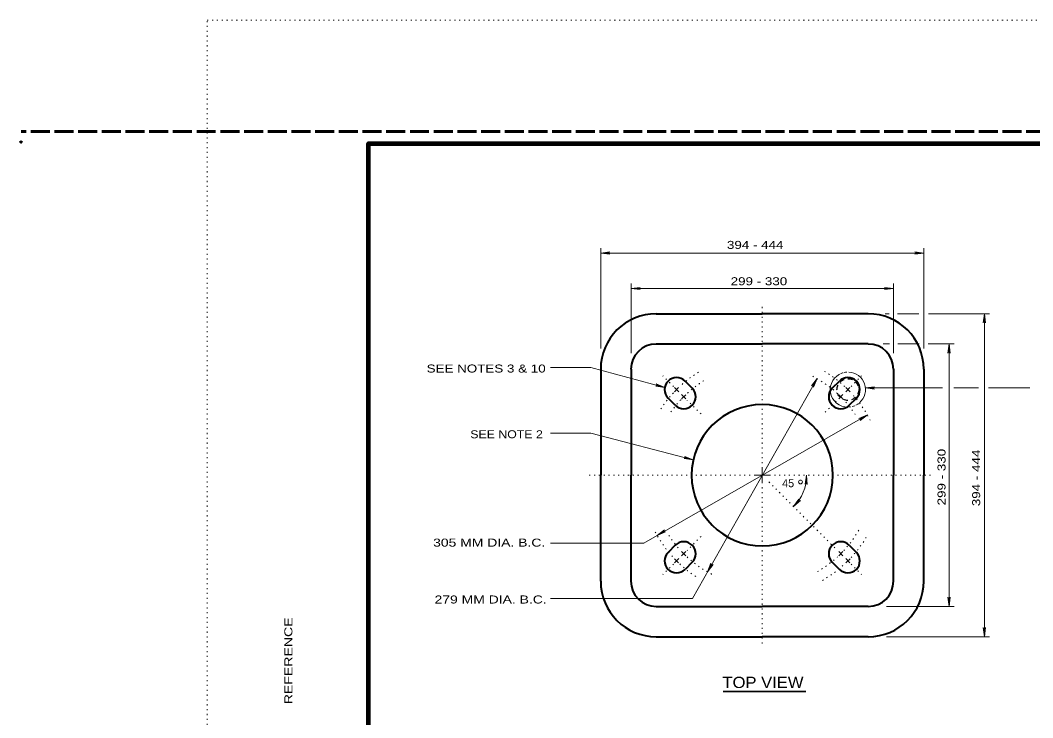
# Model space of a CAD drawing. Extents: x 312583 to 312854, y 144419 to 144597.
# Drawn here: x 312583.5 to 312679.6, y 144530.6 to 144596.8 of the extents above; entities that cross this region are included whole.
import ezdxf
from ezdxf.enums import TextEntityAlignment as Align

# ---------------------------------------------------------------- set-up
doc = ezdxf.new("R2010")
doc.units = 0
doc.header["$LTSCALE"] = 0.3
doc.header["$PDMODE"] = 32
doc.header["$PDSIZE"] = 0.15
for name, pattern in [('DOTTED', [1.5, 0.3, -1.2]), ('LONG_DASHED', [7.5, 6, -1.5]), ('SHORT_DASHED', [2.7, 1.5, -1.2])]:
    doc.linetypes.add(name, pattern=pattern)
for name, color, linetype, lineweight in [('1', 7, 'Continuous', 40), ('2', 7, 'Continuous', 13), ('62', 7, 'DOTTED', 13), ('63', 7, 'LONG_DASHED', 60)]:
    doc.layers.add(name, color=color, linetype=linetype, lineweight=lineweight)

msp = doc.modelspace()

# ---------------------------------------------------------------- linework, layer by layer
at = {"layer": '1'}
for p, q in [((312643.821, 144568.9263), (312653.8873, 144568.9263)), ((312663.946, 144568.9263), (312653.8873, 144568.9263)), ((312643.821, 144566.0513), (312653.8873, 144566.0513)), ((312663.946, 144566.0513), (312653.8873, 144566.0513)), ((312638.554, 144563.6516), (312638.554, 144553.5929)), ((312641.429, 144563.6516), (312641.429, 144553.5929)), ((312666.3457, 144563.6516), (312666.3457, 144553.5929)), ((312669.2207, 144563.6516), (312669.2207, 144553.5929)), ((312647.2327, 144561.8499), (312646.558, 144562.5246)), ((312660.5343, 144561.8499), (312661.209, 144562.5246)), ((312645.6227, 144560.2399), (312644.948, 144560.9146)), ((312662.1443, 144560.2399), (312662.819, 144560.9146)), ((312638.554, 144543.5266), (312638.554, 144553.5929)), ((312641.429, 144543.5266), (312641.429, 144553.5929)), ((312666.3457, 144543.5266), (312666.3457, 144553.5929)), ((312669.2207, 144543.5266), (312669.2207, 144553.5929)), ((312645.6227, 144546.9459), (312644.948, 144546.2636)), ((312662.1443, 144546.9459), (312662.819, 144546.2636)), ((312647.2327, 144545.3359), (312646.558, 144544.6536)), ((312660.5343, 144545.3359), (312661.209, 144544.6536)), ((312643.821, 144541.1346), (312653.8873, 144541.1346)), ((312663.946, 144541.1346), (312653.8873, 144541.1346)), ((312643.821, 144538.2596), (312653.8873, 144538.2596)), ((312663.946, 144538.2596), (312653.8873, 144538.2596))]:
    msp.add_line(p, q, dxfattribs=at)
at = {"layer": '1', "linetype": 'DOTTED', "lineweight": 13}
for p, q in [((312645.454, 144562.0186), (312644.4573, 144563.0229)), ((312662.313, 144562.0186), (312663.3097, 144563.0229)), ((312648.076, 144559.4043), (312646.742, 144560.7306)), ((312659.8597, 144559.5653), (312661.025, 144560.7306)), ((312654.5237, 144552.9489), (312661.025, 144546.4476)), ((312648.076, 144547.7816), (312646.742, 144546.4476)), ((312645.454, 144545.1596), (312644.4573, 144544.1629)), ((312662.313, 144545.1596), (312663.3097, 144544.1629))]:
    msp.add_line(p, q, dxfattribs=at)
at = {"layer": '1', "lineweight": 13}
for p, q in [((312645.96, 144561.5126), (312645.5537, 144561.9189)), ((312661.807, 144561.5126), (312662.2133, 144561.9189)), ((312646.6347, 144560.8456), (312646.2283, 144561.2519)), ((312661.14, 144560.8456), (312661.5463, 144561.2519)), ((312645.96, 144545.6733), (312645.5537, 144545.2669)), ((312646.6347, 144546.3403), (312646.2283, 144545.9339)), ((312661.14, 144546.3403), (312661.5463, 144545.9339)), ((312661.807, 144545.6733), (312662.2133, 144545.2669))]:
    msp.add_line(p, q, dxfattribs=at)
at = {"layer": '1', "lineweight": 158}
msp.add_lwpolyline([(312616.5, 144423.1446), (312616.5, 144585.0846), (312849, 144585.0846)], dxfattribs=at)
at = {"layer": '1', "linetype": 'SHORT_DASHED', "lineweight": 25}
msp.add_circle((312662.014, 144561.7215), 1.0339, dxfattribs=at)
at = {"layer": '1'}
for centre, radius, start, end in [((312643.821, 144563.6535), 5.2708, 90, 180), ((312663.946, 144563.6535), 5.2708, 0, 90), ((312643.821, 144563.6535), 2.3958, 90, 180), ((312663.946, 144563.6535), 2.3958, 0, 90), ((312645.753, 144561.7215), 1.1384, 45, 225), ((312662.014, 144561.7215), 1.1384, 315, 135), ((312646.4296, 144561.0449), 1.1384, 225, 45), ((312661.3374, 144561.0449), 1.1384, 135, 315), ((312653.8835, 144553.591), 6.7083, 90, 180), ((312653.8835, 144553.591), 6.7083, 0, 90), ((312653.8835, 144553.591), 6.7083, 180, 270), ((312653.8835, 144553.591), 6.7083, 270, 0), ((312646.4296, 144546.1371), 1.1384, 315, 135), ((312661.3374, 144546.1371), 1.1384, 45, 225), ((312645.753, 144545.4605), 1.1384, 135, 315), ((312662.014, 144545.4605), 1.1384, 225, 45), ((312643.821, 144543.5285), 5.2708, 180, 270), ((312643.821, 144543.5285), 2.3958, 180, 270), ((312663.946, 144543.5285), 5.2708, 270, 0), ((312663.946, 144543.5285), 2.3958, 270, 0)]:
    msp.add_arc(centre, radius, start, end, dxfattribs=at)
at = {"layer": '1', "linetype": 'DOTTED', "lineweight": 13}
for radius, start, end in [(11.5, 121.71451, 132.90639), (10.5417, 47.41661, 63.36905), (11.5, 47.09459, 60.18147), (10.5417, 121.71386, 132.58339), (11.5, 137.18158, 147.17965), (11.5, 26.95504, 42.81842), (10.5417, 137.23997, 147.17573), (10.5417, 33.10756, 42.76003), (11.5, 207.95114, 222.81842), (10.5417, 212.82427, 222.76003), (10.5417, 317.23939, 330.45291), (11.5, 317.18755, 330.45291), (10.5417, 227.41661, 243.86032), (10.5417, 299.81853, 312.58463), (11.5, 227.09361, 238.28549), (11.5, 299.81853, 312.90541)]:
    msp.add_arc((312653.8835, 144553.591), radius, start, end, dxfattribs=at)
at = {"layer": '1', "lineweight": 13}
for centre, radius, start, end in [((312662.014, 144561.7215), 1.6684, 119.0418, 280.06174), ((312662.014, 144561.7215), 1.6684, 105.69863, 115.35247), ((312662.014, 144561.7215), 1.6684, 93.2273, 102.59199), ((312662.014, 144561.7215), 1.6684, 311.02622, 87.10752), ((312653.8835, 144553.591), 11.5, 133.65585, 136.45218), ((312653.8835, 144553.591), 11.5, 43.54782, 46.34415), ((312653.8835, 144553.591), 10.5417, 133.51949, 136.65089), ((312653.8835, 144553.591), 10.5417, 43.34911, 46.48051), ((312662.014, 144561.7215), 1.6684, 284.29274, 293.24212), ((312662.014, 144561.7215), 1.6684, 297.30336, 307.05229), ((312653.8835, 144553.591), 11.5, 223.54782, 226.34415), ((312653.8835, 144553.591), 10.5417, 223.34911, 226.48051), ((312653.8835, 144553.591), 10.5417, 313.51949, 316.65089), ((312653.8835, 144553.591), 11.5, 313.65585, 316.45218)]:
    msp.add_arc(centre, radius, start, end, dxfattribs=at)
at = {"layer": '1'}
msp.add_point((312583.526, 144585.2246), dxfattribs=at)
at = {"layer": '2'}
for p, q in [((312638.554, 144565.6219), (312638.554, 144575.1593)), ((312638.554, 144574.6763), (312639.4203, 144574.7836)), ((312638.554, 144574.6763), (312669.2207, 144574.6763)), ((312638.554, 144574.6763), (312639.4203, 144574.5689)), ((312639.4203, 144574.7836), (312639.1443, 144574.6763)), ((312639.4203, 144574.5689), (312639.1443, 144574.6763)), ((312668.3543, 144574.7836), (312668.6303, 144574.6763)), ((312669.2207, 144574.6763), (312668.3543, 144574.7836)), ((312668.3543, 144574.5689), (312668.6303, 144574.6763)), ((312669.2207, 144574.6763), (312668.3543, 144574.5689)), ((312669.2207, 144565.6219), (312669.2207, 144575.1593)), ((312641.429, 144565.1849), (312641.429, 144571.8013)), ((312666.3457, 144565.1849), (312666.3457, 144571.8013)), ((312641.429, 144571.3183), (312642.2953, 144571.4256)), ((312641.429, 144571.3183), (312666.3457, 144571.3183)), ((312641.429, 144571.3183), (312642.2953, 144571.2109)), ((312642.2953, 144571.4256), (312642.0193, 144571.3183)), ((312642.2953, 144571.2109), (312642.0193, 144571.3183)), ((312665.4793, 144571.4256), (312665.7553, 144571.3183)), ((312666.3457, 144571.3183), (312665.4793, 144571.4256)), ((312665.4793, 144571.2109), (312665.7553, 144571.3183)), ((312666.3457, 144571.3183), (312665.4793, 144571.2109)), ((312665.5483, 144568.9263), (312665.9393, 144568.9263)), ((312666.7213, 144568.9263), (312668.7453, 144568.9263)), ((312669.673, 144568.9263), (312675.446, 144568.9263)), ((312674.9707, 144568.9263), (312674.8633, 144568.0599)), ((312674.9707, 144568.9263), (312674.9707, 144538.2596)), ((312674.9707, 144568.9263), (312675.078, 144568.0599)), ((312674.8633, 144568.0599), (312674.9707, 144568.3359)), ((312675.078, 144568.0599), (312674.9707, 144568.3359)), ((312665.349, 144566.0513), (312665.97, 144566.0513)), ((312666.752, 144566.0513), (312668.7837, 144566.0513)), ((312669.6423, 144566.0513), (312672.0957, 144566.0513)), ((312671.6127, 144566.0513), (312671.5053, 144565.1849)), ((312671.6127, 144566.0513), (312671.6127, 144541.1346)), ((312671.6127, 144566.0513), (312671.72, 144565.1849)), ((312671.5053, 144565.1849), (312671.6127, 144565.4609)), ((312671.72, 144565.1849), (312671.6127, 144565.4609)), ((312637.6263, 144563.8203), (312633.793, 144563.8203)), ((312644.6337, 144561.9343), (312637.6263, 144563.8203)), ((312643.775, 144562.0569), (312644.0663, 144562.0876)), ((312644.6337, 144561.9343), (312643.775, 144562.0569)), ((312643.8287, 144562.2639), (312644.0663, 144562.0876)), ((312644.6337, 144561.9343), (312643.8287, 144562.2639)), ((312647.2557, 144541.8936), (312659.0853, 144562.7623)), ((312659.0853, 144562.7623), (312658.564, 144562.0646)), ((312658.564, 144562.0646), (312658.794, 144562.2486)), ((312659.0853, 144562.7623), (312658.748, 144561.9573)), ((312658.748, 144561.9573), (312658.794, 144562.2486)), ((312663.6777, 144561.8729), (312664.544, 144561.9803)), ((312663.6777, 144561.8729), (312670.9917, 144561.8729)), ((312663.6777, 144561.8729), (312664.544, 144561.7656)), ((312664.544, 144561.9803), (312664.268, 144561.8729)), ((312664.544, 144561.7656), (312664.268, 144561.8729)), ((312672.0573, 144561.8729), (312674.411, 144561.8729)), ((312675.3693, 144561.8729), (312679.2947, 144561.8729)), ((312663.8617, 144559.3123), (312642.6557, 144547.1529)), ((312663.8617, 144559.3123), (312663.0567, 144558.9749)), ((312663.0567, 144558.9749), (312663.348, 144559.0209)), ((312663.8617, 144559.3123), (312663.164, 144558.7909)), ((312663.164, 144558.7909), (312663.348, 144559.0209)), ((312637.6263, 144557.5796), (312633.793, 144557.5796)), ((312647.3323, 144555.0496), (312637.6263, 144557.5796)), ((312646.4737, 144555.1646), (312646.765, 144555.1953)), ((312647.3323, 144555.0496), (312646.4737, 144555.1646)), ((312646.5273, 144555.3716), (312646.765, 144555.1953)), ((312647.3323, 144555.0496), (312646.5273, 144555.3716)), ((312653.8873, 144553.5929), (312653.8873, 144554.3596)), ((312653.8873, 144553.5929), (312653.8873, 144554.3596)), ((312653.8873, 144553.5929), (312653.1207, 144553.5929)), ((312653.8873, 144553.5929), (312654.654, 144553.5929)), ((312653.8873, 144553.5929), (312653.8873, 144552.8263)), ((312658.0963, 144553.5929), (312657.9507, 144552.7343)), ((312658.0963, 144553.5929), (312658.1577, 144552.7189)), ((312657.9507, 144552.7343), (312658.0657, 144553.0026)), ((312658.1577, 144552.7189), (312658.0657, 144553.0026)), ((312656.862, 144550.6106), (312657.368, 144551.3236)), ((312657.368, 144551.3236), (312657.2607, 144551.0476)), ((312656.862, 144550.6106), (312657.5213, 144551.1856)), ((312657.5213, 144551.1856), (312657.2607, 144551.0476)), ((312643.9053, 144547.8736), (312644.603, 144548.3949)), ((312644.603, 144548.3949), (312644.419, 144548.1649)), ((312643.9053, 144547.8736), (312644.7103, 144548.2109)), ((312644.7103, 144548.2109), (312644.419, 144548.1649)), ((312642.6557, 144547.1529), (312633.793, 144547.1529)), ((312648.6893, 144544.4236), (312649.019, 144545.2286)), ((312648.6893, 144544.4236), (312649.2107, 144545.1213)), ((312649.019, 144545.2286), (312648.9807, 144544.9373)), ((312649.2107, 144545.1213), (312648.9807, 144544.9373)), ((312647.2557, 144541.8936), (312633.793, 144541.8936)), ((312671.5053, 144542.0009), (312671.6127, 144541.7249)), ((312671.6127, 144541.1346), (312671.5053, 144542.0009)), ((312671.72, 144542.0009), (312671.6127, 144541.7249)), ((312671.6127, 144541.1346), (312671.72, 144542.0009)), ((312665.694, 144541.1346), (312672.0957, 144541.1346)), ((312674.8633, 144539.1259), (312674.9707, 144538.8499)), ((312674.9707, 144538.2596), (312674.8633, 144539.1259)), ((312675.078, 144539.1259), (312674.9707, 144538.8499)), ((312674.9707, 144538.2596), (312675.078, 144539.1259)), ((312665.694, 144538.2596), (312675.446, 144538.2596))]:
    msp.add_line(p, q, dxfattribs=at)
at = {"layer": '2', "linetype": 'DOTTED'}
for p, q in [((312653.8873, 144554.7429), (312653.8873, 144569.5856)), ((312652.7373, 144553.5929), (312637.4577, 144553.5929)), ((312655.0373, 144553.5929), (312670.0257, 144553.5929)), ((312653.8873, 144552.4429), (312653.8873, 144537.6003))]:
    msp.add_line(p, q, dxfattribs=at)
at = {"layer": '2', "lineweight": 35}
msp.add_line((312650.1687, 144533.0693), (312658.0158, 144533.0693), dxfattribs=at)
at = {"layer": '2'}
msp.add_circle((312657.5135, 144552.9508), 0.1797, dxfattribs=at)
msp.add_arc((312653.8835, 144553.591), 4.2148, 315, 0, dxfattribs=at)
at = {"layer": '62'}
for p, q in [((312601.2, 144596.7846), (312853.5, 144596.7846)), ((312601.2, 144418.5846), (312601.2, 144596.7846))]:
    msp.add_line(p, q, dxfattribs=at)
at = {"layer": '63'}
msp.add_line((312851.75, 144586.2246), (312583.526, 144586.2246), dxfattribs=at)

# ---------------------------------------------------------------- texts
at = {"layer": '1', "width": 1.3}
msp.add_text('REFERENCE                                                              ', height=0.7682, rotation=90, dxfattribs=at).set_placement((312609.2854, 144531.8549))
at = {"layer": '2'}
for s, width, p in [('394 - 444', 1.25, (312650.5329, 144575.0779)), ('299 - 330', 1.25, (312650.8859, 144571.628)), ('SEE NOTES 3 & 10', 1.25, (312622.0279, 144563.341)), ('SEE NOTE 2', 1.15, (312626.1691, 144557.1002)), ('305 MM DIA. B.C.', 1.3, (312622.6418, 144546.8139)), ('279 MM DIA. B.C.', 1.3, (312622.7785, 144541.4143))]:
    msp.add_text(s, height=0.76, dxfattribs=dict(at, width=width)).set_placement(p)
at = {"layer": '2', "width": 1.25}
for s, p in [('299 - 330', (312671.2822, 144550.7282)), ('394 - 444 ', (312674.5701, 144550.6511))]:
    msp.add_text(s, height=0.76, rotation=90, dxfattribs=at).set_placement(p)
at = {"layer": '2'}
msp.add_text('45', height=0.76, dxfattribs=at).set_placement((312655.7771, 144552.4559))
at = {"layer": '2', "width": 1.1}
msp.add_text('TOP VIEW', height=1.07, dxfattribs=at).set_placement((312653.953, 144533.3911), align=Align.CENTER)

doc.saveas('drawing.dxf')
